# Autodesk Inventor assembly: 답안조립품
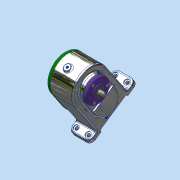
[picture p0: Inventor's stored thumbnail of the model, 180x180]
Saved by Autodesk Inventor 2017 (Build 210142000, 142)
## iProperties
Part Number: 답안조립품
Material: 일반
Document SubType Name: Assembly
Designer: MRC
Author: MRC
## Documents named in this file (19)
- C:\Users\MRC\Desktop\710609V1002\답안조립품.iam
- C:\Users\MRC\Desktop\710609V1002\본체.ipt
- C:\Users\MRC\Desktop\710609V1002\개스킷 A.ipt
- C:\Users\MRC\Desktop\710609V1002\개스킷 B.ipt
- C:\Users\MRC\Desktop\710609V1002\베어링 6001.ipt
- 베어링 6001.ipt
- C:\Users\MRC\Desktop\710609V1002\베어링 6002.ipt
- 베어링 6002.ipt
- C:\Users\MRC\Desktop\710609V1002\볼트 M4.ipt
- C:\Users\MRC\Desktop\710609V1002\스퍼기어 A.ipt
- C:\Users\MRC\Desktop\710609V1002\스퍼기어 B.ipt
- C:\Users\MRC\Desktop\710609V1002\오일 실 12 22 7.ipt
- C:\Users\MRC\Desktop\710609V1002\축 A.ipt
- C:\Users\MRC\Desktop\710609V1002\축 B.ipt
- C:\Users\MRC\Desktop\710609V1002\칼라.ipt
- C:\Users\MRC\Desktop\710609V1002\커버 A.ipt
- C:\Users\MRC\Desktop\710609V1002\커버 B.ipt
- C:\Users\MRC\Desktop\710609V1002\키 4 x 4 x 12.ipt
- C:\Users\MRC\Desktop\710609V1002\키 5 x 5 x 12.ipt
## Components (2 placed, 2 different names)
1. 개스킷 A:1
2. 개스킷 B:1
